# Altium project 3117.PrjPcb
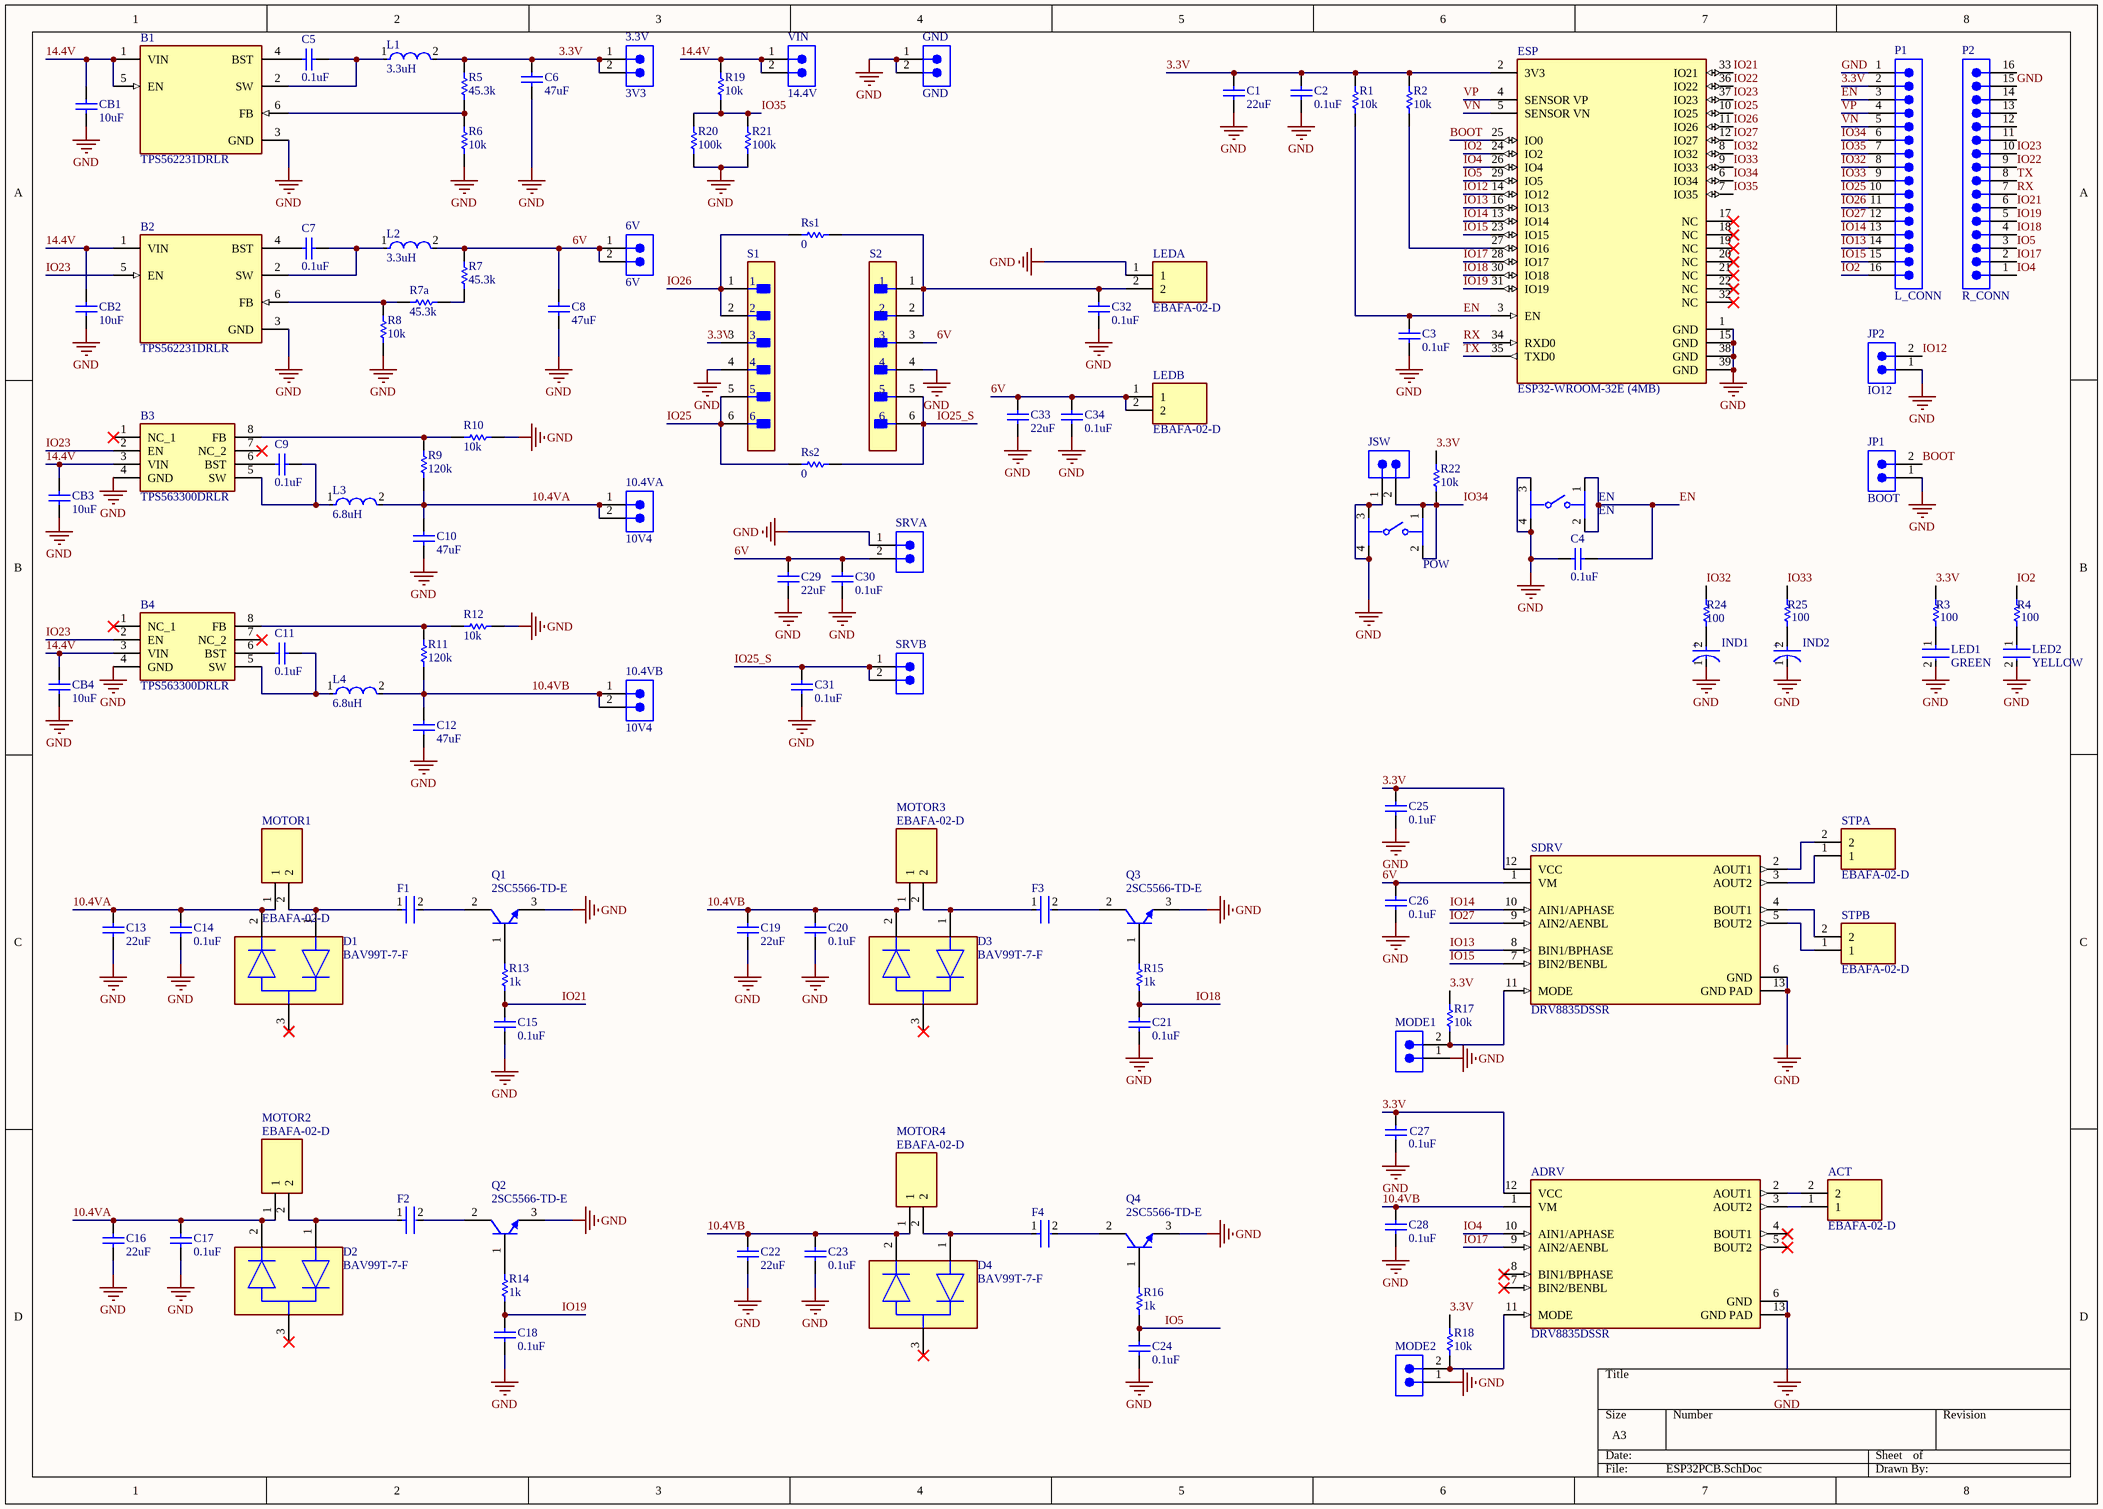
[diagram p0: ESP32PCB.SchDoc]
1 sheet, 120 parts. Net scope: global (net labels, ports and power ports of the same name join across sheets).
Board file: ESP32PCB.PcbDoc

## Sheet ESP32PCB.SchDoc
size A3; SheetNumber: 1; SheetTotal: 1

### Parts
3.3V  3V3  [61300211121]
6V  6V  [61300211121]
10.4VA  10V4  [61300211121]
10.4VB  10V4  [61300211121]
ACT  EBAFA-02-D  [EBAFA02D]
ADRV  DRV8835DSSR  [FP-DSS0012A-IPC_A]
B1  TPS562231DRLR  [FP-DRL0006A-MFG]
B2  TPS562231DRLR  [FP-DRL0006A-MFG]
B3  TPS563300DRLR  [TPS62932DRLR]
B4  TPS563300DRLR  [TPS62932DRLR]
C1  22uF  [CAPC2013X145X50ML20T25]
C2  0.1uF  [CAPC2013X145X50ML20T25]
C3  0.1uF  [CAPC2013X145X50ML20T25]
C4  0.1uF  [CAPC2013X145X50ML20T25]
C5  0.1uF  [CAPC2013X145X50ML20T25]
C6  47uF  [CAPC2013X145X50ML20T25]
C7  0.1uF  [CAPC2013X145X50ML20T25]
C8  47uF  [CAPC2013X145X50ML20T25]
C9  0.1uF  [CAPC2013X145X50ML20T25]
C10  47uF  [CAPC2013X145X50ML20T25]
C11  0.1uF  [CAPC2013X145X50ML20T25]
C12  47uF  [CAPC2013X145X50ML20T25]
C13  22uF  [CAPC2013X145X50ML20T25]
C14  0.1uF  [CAPC2013X145X50ML20T25]
C15  0.1uF  [CAPC2013X145X50ML20T25]
C16  22uF  [CAPC2013X145X50ML20T25]
C17  0.1uF  [CAPC2013X145X50ML20T25]
C18  0.1uF  [CAPC2013X145X50ML20T25]
C19  22uF  [CAPC2013X145X50ML20T25]
C20  0.1uF  [CAPC2013X145X50ML20T25]
C21  0.1uF  [CAPC2013X145X50ML20T25]
C22  22uF  [CAPC2013X145X50ML20T25]
C23  0.1uF  [CAPC2013X145X50ML20T25]
C24  0.1uF  [CAPC2013X145X50ML20T25]
C25  0.1uF  [CAPC2013X145X50ML20T25]
C26  0.1uF  [CAPC2013X145X50ML20T25]
C27  0.1uF  [CAPC2013X145X50ML20T25]
C28  0.1uF  [CAPC2013X145X50ML20T25]
C29  22uF  [CAPC2013X145X50ML20T25]
C30  0.1uF  [CAPC2013X145X50ML20T25]
C31  0.1uF  [CAPC2013X145X50ML20T25]
C32  0.1uF  [CAPC2013X145X50ML20T25]
C33  22uF  [CAPC2013X145X50ML20T25]
C34  0.1uF  [CAPC2013X145X50ML20T25]
CB1  10uF  [CAPC2013X145X50ML20T25]
CB2  10uF  [CAPC2013X145X50ML20T25]
CB3  10uF  [CAPC2013X145X50ML20T25]
CB4  10uF  [CAPC2013X145X50ML20T25]
D1  BAV99T-7-F  [FP-SOT523-MFG]
D2  BAV99T-7-F  [FP-SOT523-MFG]
D3  BAV99T-7-F  [FP-SOT523-MFG]
D4  BAV99T-7-F  [FP-SOT523-MFG]
EN  EN  [FP-PTS645SM43SMTR92LFS-MFG]
ESP  ESP32-WROOM-32E (4MB)  [FP-ESP32-WROOM-32E_4MB-MFG]
F1  (no value)  [FP-GRM319-0_15-IPC_C]
F2  (no value)  [FP-GRM319-0_15-IPC_C]
F3  (no value)  [FP-GRM319-0_15-IPC_C]
F4  (no value)  [FP-GRM319-0_15-IPC_C]
GND  GND  [61300211121]
IND1  (no value)  [FP-OS-CON-TH-E12-d_0_6-MFG]
IND2  (no value)  [FP-OS-CON-TH-E12-d_0_6-MFG]
JP1  BOOT  [61300211121]
JP2  IO12  [61300211121]
JSW  (no value)  [61300211121]
L1  3.3uH  [FP-NR4012-MFG]
L2  3.3uH  [FP-NR4012-MFG]
L3  6.8uH  [FP-NRS5030-H_3_1-MFG]
L4  6.8uH  [FP-NRS5030-H_3_1-MFG]
LED1  GREEN  [FP-1812-L_4_5_0_3-W_3_2_0-MFG]
LED2  YELLOW  [FP-1812-L_4_5_0_3-W_3_2_0-MFG]
LEDA  EBAFA-02-D  [EBAFA02D]
LEDB  EBAFA-02-D  [EBAFA02D]
MODE1  (no value)  [61300211121]
MODE2  (no value)  [61300211121]
MOTOR1  EBAFA-02-D  [EBAFA02D]
MOTOR2  EBAFA-02-D  [EBAFA02D]
MOTOR3  EBAFA-02-D  [EBAFA02D]
MOTOR4  EBAFA-02-D  [EBAFA02D]
P1  L_CONN  [61301611121]
P2  R_CONN  [61301611121]
POW  (no value)  [FP-PTS645SM43SMTR92LFS-MFG]
Q1  2SC5566-TD-E  [ONSC-SOT-89_PCP-1-3-419AU_V]
Q2  2SC5566-TD-E  [ONSC-SOT-89_PCP-1-3-419AU_V]
Q3  2SC5566-TD-E  [ONSC-SOT-89_PCP-1-3-419AU_V]
Q4  2SC5566-TD-E  [ONSC-SOT-89_PCP-1-3-419AU_V]
R1  10k  [RESC2013X60X35ML10T20]
R2  10k  [RESC2013X60X35ML10T20]
R3  100  [RESC2013X60X35ML10T20]
R4  100  [RESC2013X60X35ML10T20]
R5  45.3k  [RESC2013X50X30LL20T20]
R6  10k  [RESC2013X50X30LL20T20]
R7  45.3k  [RESC2013X50X30LL20T20]
R7a  45.3k  [RESC2013X50X30LL20T20]
R8  10k  [RESC2013X50X30LL20T20]
R9  120k  [RESC2013X50X30LL20T20]
R10  10k  [RESC2013X50X30LL20T20]
R11  120k  [RESC2013X50X30LL20T20]
R12  10k  [RESC2013X50X30LL20T20]
R13  1k  [RESC2013X50X30LL20T20]
R14  1k  [RESC2013X50X30LL20T20]
R15  1k  [RESC2013X50X30LL20T20]
R16  1k  [RESC2013X50X30LL20T20]
R17  10k  [RESC2013X50X30LL20T20]
R18  10k  [RESC2013X50X30LL20T20]
R19  10k  [RESC2013X50X30LL20T20]
R20  100k  [RESC2013X50X30LL20T20]
R21  100k  [RESC2013X50X30LL20T20]
R22  10k  [RESC2013X60X35ML10T20]
R24  100  [RESC2013X60X35ML10T20]
R25  100  [RESC2013X60X35ML10T20]
Rs1  0  [RESC2013X50X30LL20T20]
Rs2  0  [RESC2013X50X30LL20T20]
S1  (no value)  [FP-22-28-4060-MFG]
S2  (no value)  [FP-22-28-4060-MFG]
SDRV  DRV8835DSSR  [FP-DSS0012A-IPC_A]
SRVA  (no value)  [61300211121]
SRVB  (no value)  [61300211121]
STPA  EBAFA-02-D  [EBAFA02D]
STPB  EBAFA-02-D  [EBAFA02D]
VIN  14.4V  [61300211121]

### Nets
GND: ADRV.6(GND) ADRV.13(GND_PAD) B1.3(GND) B2.3(GND) B3.4(GND) B4.4(GND) C1.1 C2.1 C3.1 C4.2 C6.2 C8.2 C10.2 C12.2 C13.2 C14.2 C15.2 C16.2 C17.2 C18.2 C19.2 C20.2 C21.2 C22.2 C23.2 C24.2 C25.2 C26.2 C27.2 C28.2 C29.2 C30.2 C31.2 C32.2 C33.2 C34.2 CB1.2 CB2.2 CB3.2 CB4.2 EN.3 EN.4 ESP.1(GND) ESP.15(GND) ESP.38(GND) ESP.39(GND) GND.1 GND.2 IND1.1(C) IND2.1(C) JP1.1 JP2.1 JSW.1 LED1.2 LED2.2 LEDA.1 MODE1.1 MODE2.1 P1.1 P2.15 POW.3 POW.4 Q1.3(E) Q2.3(E) Q3.3(E) Q4.3(E) R6.2 R8.2 R10.2 R12.2 R20.2 R21.2 S1.4 S2.4 SDRV.6(GND) SDRV.13(GND_PAD) SRVA.1
3.3V: 3.3V.1 3.3V.2 ADRV.12(VCC) C1.2 C2.2 C6.1 C25.1 C27.1 ESP.2(3V3) L1.2 P1.2 R1.1 R2.1 R3.1 R5.1 R17.2 R18.2 R22.1 S1.3 SDRV.12(VCC)
6V: 6V.1 6V.2 C8.1 C26.1 C29.1 C30.1 C33.1 C34.1 L2.2 LEDB.1 LEDB.2 R7.1 S2.3 SDRV.1(VM) SRVA.2
10.4VA: 10.4VA.1 10.4VA.2 C10.1 C13.1 C14.1 C16.1 C17.1 D1.2 D2.2 L3.2 MOTOR1.1 MOTOR2.1 R9.1
10.4VB: 10.4VB.1 10.4VB.2 ADRV.1(VM) C12.1 C19.1 C20.1 C22.1 C23.1 C28.1 D3.2 D4.2 L4.2 MOTOR3.1 MOTOR4.1 R11.1
14.4V: B1.1(VIN) B1.5(EN) B2.1(VIN) B3.3(VIN) B4.3(VIN) CB1.1 CB2.1 CB3.1 CB4.1 R19.1 VIN.1 VIN.2
BOOT: ESP.25(IO0) JP1.2
EN: C3.2 C4.1 EN.1 EN.2 ESP.3(EN) P1.3 R1.2
IO2: ESP.24(IO2) P1.16 R4.1
IO4: ADRV.10(AIN1/APHASE) ESP.26(IO4) P2.1
IO5: C24.1 ESP.29(IO5) P2.3 R16.1
IO12: ESP.14(IO12) JP2.2
IO13: ESP.16(IO13) P1.14 SDRV.8(BIN1/BPHASE)
IO14: ESP.13(IO14) P1.13 SDRV.10(AIN1/APHASE)
IO15: ESP.23(IO15) P1.15 SDRV.7(BIN2/BENBL)
IO17: ADRV.9(AIN2/AENBL) ESP.28(IO17) P2.2
IO18: C21.1 ESP.30(IO18) P2.4 R15.1
IO19: C18.1 ESP.31(IO19) P2.5 R14.1
IO21: C15.1 ESP.33(IO21) P2.6 R13.1
IO22: ESP.36(IO22) P2.9
IO23: B2.5(EN) B3.2(EN) B4.2(EN) ESP.37(IO23) P2.10
IO25: ESP.10(IO25) P1.10 Rs2.1 S1.5 S1.6
IO25_S: C31.1 Rs2.2 S2.5 S2.6 SRVB.1 SRVB.2
IO26: ESP.11(IO26) P1.11 Rs1.1 S1.1 S1.2
IO27: ESP.12(IO27) P1.12 SDRV.9(AIN2/AENBL)
IO32: ESP.8(IO32) P1.8 R24.1
IO33: ESP.9(IO33) P1.9 R25.1
IO34: ESP.6(IO34) JSW.2 P1.6 POW.1 POW.2 R22.2
IO35: ESP.7(IO35) P1.7 R19.2 R20.1 R21.1
RX: ESP.34(RXD0) P2.7
TX: ESP.35(TXD0) P2.8
VN: ESP.5(SENSOR_VN) P1.5
VP: ESP.4(SENSOR_VP) P1.4
NetACT_1: ACT.1 ADRV.3(AOUT2)
NetACT_2: ACT.2 ADRV.2(AOUT1)
NetADRV_11: ADRV.11(MODE) MODE2.2 R18.1
NetB1_2: B1.2(SW) C5.1 L1.1
NetB1_4: B1.4(BST) C5.2
NetB1_6: B1.6(FB) R5.2 R6.1
NetB2_2: B2.2(SW) C7.1 L2.1
NetB2_4: B2.4(BST) C7.2
NetB2_6: B2.6(FB) R7a.1 R8.1
NetB3_5: B3.5(SW) C9.1 L3.1
NetB3_6: B3.6(BST) C9.2
NetB3_8: B3.8(FB) R9.2 R10.1
NetB4_5: B4.5(SW) C11.1 L4.1
NetB4_6: B4.6(BST) C11.2
NetB4_8: B4.8(FB) R11.2 R12.1
NetC32_1: C32.1 LEDA.2 Rs1.2 S2.1 S2.2
NetD1_1: D1.1 F1.1 MOTOR1.2
NetD2_1: D2.1 F2.1 MOTOR2.2
NetD3_1: D3.1 F3.1 MOTOR3.2
NetD4_1: D4.1 F4.1 MOTOR4.2
NetESP_27: ESP.27(IO16) R2.2
NetF1_2: F1.2 Q1.2(C)
NetF2_2: F2.2 Q2.2(C)
NetF3_2: F3.2 Q3.2(C)
NetF4_2: F4.2 Q4.2(C)
NetIND1_2: IND1.2(A) R24.2
NetIND2_2: IND2.2(A) R25.2
NetLED1_1: LED1.1 R3.2
NetLED2_1: LED2.1 R4.2
NetMODE1_2: MODE1.2 R17.1 SDRV.11(MODE)
NetQ1_1: Q1.1(B) R13.2
NetQ2_1: Q2.1(B) R14.2
NetQ3_1: Q3.1(B) R15.2
NetQ4_1: Q4.1(B) R16.2
NetR7_2: R7.2 R7a.2
NetSDRV_2: SDRV.2(AOUT1) STPA.2
NetSDRV_3: SDRV.3(AOUT2) STPA.1
NetSDRV_4: SDRV.4(BOUT1) STPB.2
NetSDRV_5: SDRV.5(BOUT2) STPB.1

Not connected (* = marked no-connect by the designer): ADRV 4(BOUT1)* 5(BOUT2)* 7(BIN2/BENBL)* 8(BIN1/BPHASE)*; B3 1(NC_1)* 7(NC_2)*; B4 1(NC_1)* 7(NC_2)*; D1 3*; D2 3*; D3 3*; D4 3*; ESP 17(NC)* 18(NC)* 19(NC)* 20(NC)* 21(NC)* 22(NC)* 32(NC)*; P2 11 12 13 14 16

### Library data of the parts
3.3V 6V 10.4VA 10.4VB GND JP1 JP2 JSW MODE1 MODE2 SRVA SRVB VIN = CMP-1712-00002-6: NexarPartId: 20081794; Number of Contacts: 2; Pitch: 2.54mm; Connector Type: Male Pin; Voltage Rating: 250V; Current Rating: 3A; Gender: Male; Contact Resistance: 20mΩ
ACT LEDA LEDB MOTOR1-MOTOR4 STPA STPB = EBAFA-02-D: Connector; Manufacturer_Name: Adam Tech
ADRV SDRV = CMP-00024-00007-1: Brush DC Motor Controller, 1.5A, PDSO12; Nominal Supply Voltage: 3V
B1 B2 = CMP-04918-000372-1: POWER MANAGEMENT
B3 B4 = TPS563300DRLR: Integrated Circuit; Manufacturer_Name: Texas Instruments
C1-C34 CB1-CB4 = CMP-1036-04819-2: Part Number: C0805C225K9PACTU; Manufacturer: Kemet
D1-D4 = CMP-12791-000024-1: DIODE ARRAY GP 85V 75MA SOT523; Manufacturer: Diodes Inc.; Capacitance: 1.5pF; Value: 1.5pF; Standoff Height: 0mm; Peak Reverse Current: 2uA; Max Surge Forward Current: 0.5A; Max Junction Temp: +150°C
EN POW = CMP-2000-05160-2: SWITCH TACTILE SPST-NO 0.05A 12V; Contact Resistance: 100mR; Throw Configuration: SPST; Illumination Type: Non-Illuminated; Mechanical Life: 100000Cycles; Current Rating: 50mA; Switch Function: Off-Mom; Actuator Length: 0.85mm; Actuator Material: Nylon; Actuator Type: Standard; Operating Force: 160gf
ESP = CMP-194065-000026-1: RX TXRX MOD WIFI TRACE ANT SMD
F1-F4 = CMP-1037-03764-2: Chip Multilayer Ceramic Capacitors for General Purpose, 1206, 22000pF, C0G, 30ppm/°C, 5%, 50V; Capacitance: 22nF; Insulation Resistance: 10GR
IND1 IND2 = CMP-05428-001155-1: Conductive Polymer Aluminum Solid Capacitors (OS-CON) 270uF ±20% 16V RADIAL TH 8x12mm; Dissipation Factor: 10%; Leakage Current: 864uA; Lead Diameter: 0.6mm; Polarity: Polar; Ripple Current: 5A; Life (Hours): 5000Hour; ESR (Equivalent Series Resistance): 11mR
L1 L2 = CMP-14484-001001-1: SMD Power Inductors 3.3uH ±20% 1.4A 84mΩ; Self Resonant Frequency: 60MHz; Max DC Current: 1.7A; DC Resistance (DCR): 84mR; Test Frequency: 100kHz; Core Material: Ferrite; Shielding: Shielded
L3 L4 = CMP-14484-000674-1: Inductor Power Shielded Wirewound 6.8uH 20% 100KHz Ferrite 2.3A 67.6mΩ DCR T/R; Saturation Current: 2.5A; Self Resonant Frequency: 22MHz; DC Resistance (DCR): 52mR
LED1 LED2 = CMP-1040-01548-3: General Purpose Ceramic Capacitor, 1812, 470nF, 10%, X7R, 15%, 100V; Dissipation Factor: 2.5%
P1 P2 = CMP-1502-01095-4: NexarPartId: 32855548; Voltage Rating: 250V; Connector Type: Male Pin; Current Rating: 3A; Contact Resistance: 20mΩ; Number of Contacts: 16; Gender: Male; Pitch: 2.54mm
Q1-Q4 = CMP-1048-00945-1: Bipolar Transistor, 50 V, 4 A, Low VCE(sat), NPN Single, 3-Pin SOT-89, Pb-Free, Tape and Reel; Manufacturer: On Semiconductor; IC Continuous (A): 4
R1-R4 R22 R24 R25 = CMP-2100-03671-1: Chip Resistor, 1 KOhm, +/- 1%, 125 mW, -55 to 155 degC, 0805 (2012 Metric), RoHS, Tape and Reel; Manufacturer: Yageo; Temperature Coefficient: 100ppm/degreesC; Voltage Rating (DC): 150V; Max Power Dissipation: 125mW; Resistance: 1KOhm
R5-R7 R7a R8-R21 Rs1 Rs2 = CMP-2001-04896-1: Manufacturer: Vishay Dale; Part Number: CRCW08050000Z0EA
S1 S2 = CMP-04776-000763-1: CONN HEADER VERT 6POS 2.54MM; Voltage Rating: 250V; Current Rating: 4A; Number of Contacts: 6; Max Voltage Rating (DC): 250.25kV; Gender: Male; Contact Resistance: 20mR; Connector Type: Male Pin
